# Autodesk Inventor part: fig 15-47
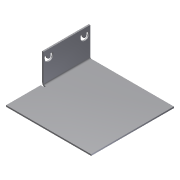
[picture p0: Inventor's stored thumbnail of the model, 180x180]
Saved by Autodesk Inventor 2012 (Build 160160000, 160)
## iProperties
Created: 2005-03
Part Number: fig 15-47
Document SubType Name: Sheet Metal
Designer: CADCIM
Manufacturer: Standard
Standards Organization: Custom
Density: 1 g/cm^3
Sheet Metal Rule: Default
Material: Default
Author: CADCIM
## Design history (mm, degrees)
node "Face1"
  sketch "Sketch1"
    geometry: L1 (-29, -26)-(30, -26); L2 (30, -26)-(30, 31.375); L3 (30, 31.375)-(-29, 31.375); L4 (-29, 31.375)-(-29, -26)
    constraints: 8 end point, 2 parallel, 1 horizontal, 1 perpendicular
node "Flange1"
sketch "Sketch4"
  geometry: L1 (3.278, 0.812)-(4.721, 0.812); L2 (4.721, 6.681)-(3.278, 6.681); L3 (3.278, 4.946)-(4.721, 4.946); L4 (4.721, 2.546)-(3.278, 2.546); L5 (3.278, 0.812)-(3.278, 2.546); L6 (3.278, 4.946)-(3.278, 6.681); L7 (3.278, 31.563)-(4.721, 31.563); L8 (4.721, 25.694)-(3.278, 25.694); L9 (3.278, 27.429)-(4.721, 27.429); L10 (4.721, 29.829)-(3.278, 29.829); L11 (3.278, 31.563)-(3.278, 29.829); L12 (3.278, 27.429)-(3.278, 25.694); A1 r 2.935 centre (4.721, 3.746) between (4.721, 0.812) and (4.721, 6.681); A2 r 1.2 centre (4.721, 3.746) between (4.721, 2.546) and (4.721, 4.946); A3 r 2.935 centre (4.721, 28.629) between (4.721, 25.694) and (4.721, 31.563); A4 r 1.2 centre (4.721, 28.629) between (4.721, 27.429) and (4.721, 29.829)
  constraints: 24 end point, 8 point on circle, 4 centre point, 3 equal length, 2 tangent, 1 horizontal, 1 perpendicular, 1 vertical alignment, 2 other
cut "Cut1" sketch "Sketch4" dims "d20" = 1 (= Thickness), "d21" = 0
body "Solid1"
face "Plate1" dims "Thickness" = 1
sketch "Sketch2"
  geometry: L1 (25, 0)-(57.375, 0); L2 (57.375, 0)-(57.375, 20); L3 (57.375, 20)-(25, 20); L4 (25, 20)-(25, 0)
  constraints: 8 end point
face "Plate2" dims "d1" = 0, "d2" = 25, "d3" = 1 (= BendReliefWidth), "d5" = 2 (= MinimumRemnant), "d7" = 20, "d8" = 90 deg, "d9" = 1 (= BendRadius), "Thickness" = 1
bend "Bend1" dims "d3" = 1 (= BendReliefWidth), "d4" = 0.5 (= BendReliefDepth), "d5" = 2 (= MinimumRemnant), "d6" = 1 (= BendRadius), "d7" = 20, "d8" = 90 deg, "d9" = 1 (= BendRadius), "SeamGap" = 0.01, "Thickness" = 1
other parameters: "BendRadius" = 1 (= Thickness), "BendReliefWidth" = 1 (= Thickness), "BendReliefDepth" = 0.5 (= 0.5 x Thickness), "CornerReliefSize" = 4 (= 4 x Thickness), "MinimumRemnant" = 2 (= 2 x Thickness), "TransitionRadius" = 1 (= BendRadius), "d0" = 1 (= BendRadius), "JacobiRadiusSize" = 1 (= Thickness), "GapSize" = 1 (= Thickness)
